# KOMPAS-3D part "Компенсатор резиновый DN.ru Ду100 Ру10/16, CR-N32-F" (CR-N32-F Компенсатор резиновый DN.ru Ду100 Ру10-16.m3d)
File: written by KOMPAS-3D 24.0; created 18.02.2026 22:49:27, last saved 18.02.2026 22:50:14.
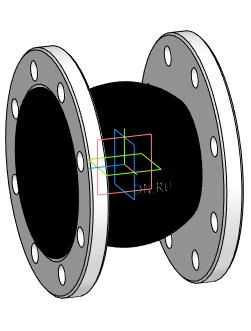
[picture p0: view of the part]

Document properties: Автор: DN.RU; Полное имя файла: D:\PROJECT CAD\DN.RU\...178(2)(ACTUALE). CR-N32-F Компенсатор резиновый DN.ru Ру10-16\CR-N32-F Компенсатор резиновый DN.ru Ру10-16\DN100\CR-N32-F Компенсатор резиновый DN.ru Ду100 Ру10-16 (2d).m3d

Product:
- Body: Твердое тело2  | qty 1
    Масса: 13.381675
- Part/product: Компенсатор резиновый DN.ru Ду100 Ру10/16  | designation CR-N32-F
    Масса: 9
    Раздел спецификации: Прочие изделия
    Комментарий: D140-02394
    Примечание: D140-02379
    additional columns: Типовые

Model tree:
1. Твердое тело2  (labels: Твердое тело2)

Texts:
  CR-N32-F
